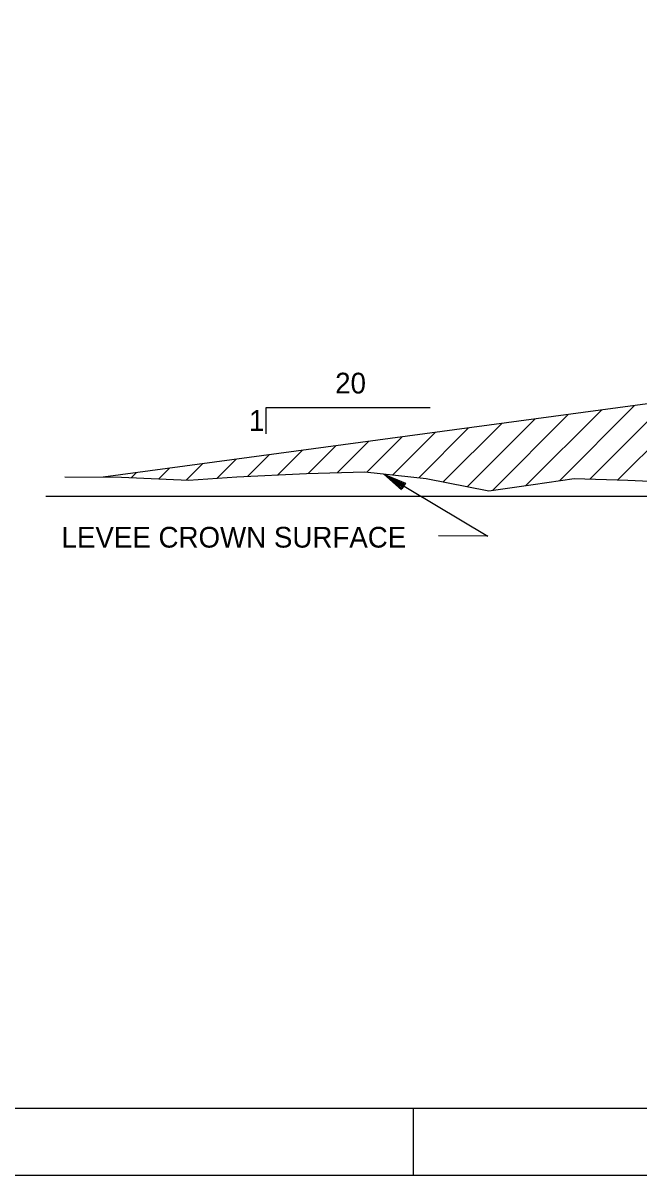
# Model space of a CAD drawing. Extents: x 2127959 to 2137375, y 2146193 to 2153470.
# Drawn here: x 2129335 to 2130315, y 2146193 to 2148025 of the extents above; entities that cross this region are included whole.
import ezdxf

# ---------------------------------------------------------------- set-up
doc = ezdxf.new("R2010")
doc.units = 0
for name, color, linetype in [('Level 1', 7, 'Continuous'), ('Level 3', 7, 'Continuous'), ('Level 5', 7, 'Continuous'), ('Level 50', 7, 'Continuous')]:
    doc.layers.add(name, color=color, linetype=linetype)

msp = doc.modelspace()

# ---------------------------------------------------------------- linework, layer by layer
at = {"layer": 'Level 1'}
for p, q in [((2131119.144, 2147525.847), (2129462.645, 2147303.347)), ((2129371.61, 2147272.911), (2133121.44, 2147272.911)), ((2130073.989, 2147209.377), (2129996.036, 2147209.918)), ((2128280.166, 2146300.478), (2136678.776, 2146300.478)), ((2129956.203, 2146192.626), (2129956.203, 2146300.478))]:
    msp.add_line(p, q, dxfattribs=at)
msp.add_lwpolyline([(2127959.193, 2153469.025), (2137374.681, 2153469.025), (2137374.681, 2146193.484), (2127959.193, 2146193.484)], close=True, dxfattribs=at)
at = {"layer": 'Level 3'}
for p, q in [((2129982.581, 2147413.45), (2129721.11, 2147413.45)), ((2129721.11, 2147413.45), (2129721.11, 2147372.009))]:
    msp.add_line(p, q, dxfattribs=at)
msp.add_lwpolyline([(2129908.45, 2147308.381), (2130073.989, 2147209.377)], dxfattribs=at)
at = {"layer": 'Level 5'}
for p, q in [((2130281.191, 2147299.02), (2130413.193, 2147431.023)), ((2130188.182, 2147297.44), (2130307.575, 2147416.838)), ((2130236.642, 2147300.191), (2130360.385, 2147423.929)), ((2130041.609, 2147288.015), (2130149.152, 2147395.559)), ((2130081.446, 2147282.135), (2130201.957, 2147402.645)), ((2130134.76, 2147289.736), (2130254.769, 2147409.74)), ((2129923.188, 2147306.737), (2129990.727, 2147374.276)), ((2129964.317, 2147302.154), (2130043.533, 2147381.369)), ((2130003.379, 2147295.498), (2130096.345, 2147388.462)), ((2129835.437, 2147310.419), (2129885.112, 2147360.089)), ((2129882.054, 2147311.324), (2129937.921, 2147367.184)), ((2129692.581, 2147304.709), (2129726.687, 2147338.814)), ((2129740.457, 2147306.869), (2129779.494, 2147345.901)), ((2129788.298, 2147308.996), (2129832.301, 2147352.998)), ((2129595.186, 2147298.739), (2129621.07, 2147324.625)), ((2129643.93, 2147301.769), (2129673.877, 2147331.719)), ((2129401.667, 2147303.908), (2129491.94, 2147303.076)), ((2129491.94, 2147303.076), (2129598.251, 2147298.615)), ((2129507.438, 2147302.424), (2129515.452, 2147310.437)), ((2129551.309, 2147300.583), (2129568.262, 2147317.533)), ((2129598.251, 2147298.615), (2129674.932, 2147303.908)), ((2129674.932, 2147303.908), (2129786.119, 2147308.929)), ((2129786.119, 2147308.929), (2129878.484, 2147311.72)), ((2129878.484, 2147311.72), (2129976.079, 2147300.843)), ((2129976.079, 2147300.843), (2130075.765, 2147281.325)), ((2130146.174, 2147291.365), (2130211.7, 2147300.843)), ((2130211.7, 2147300.843), (2130296.744, 2147298.615)), ((2130075.765, 2147281.325), (2130146.174, 2147291.365)), ((2130296.744, 2147298.615), (2130380.398, 2147294.43))]:
    msp.add_line(p, q, dxfattribs=at)
at = {"layer": 'Level 50'}
for p, q in [((2129908.812, 2147308.132), (2129908.812, 2147308.132)), ((2129917.497, 2147302.618), (2129917.497, 2147302.618))]:
    msp.add_line(p, q, dxfattribs=at)
msp.add_lwpolyline([(2129936.764, 2147283.131), (2129908.812, 2147308.132), (2129943.307, 2147293.507), (2129937.703, 2147284.639), (2129917.497, 2147302.618), (2129940.916, 2147292.665), (2129937.318, 2147286.993), (2129925.831, 2147297.303), (2129938.537, 2147291.859), (2129937.04, 2147289.514), (2129934.523, 2147291.813)], dxfattribs=at)

# ---------------------------------------------------------------- texts
at = {"layer": 'Level 1'}
for s, p in [('20', (2129831.496, 2147436.144)), ('1', (2129694.284, 2147376.695)), ('LEVEE CROWN SURFACE', (2129396.414, 2147191.214))]:
    msp.add_text(s, height=32.931, dxfattribs=at).set_placement(p)

doc.saveas('drawing.dxf')
